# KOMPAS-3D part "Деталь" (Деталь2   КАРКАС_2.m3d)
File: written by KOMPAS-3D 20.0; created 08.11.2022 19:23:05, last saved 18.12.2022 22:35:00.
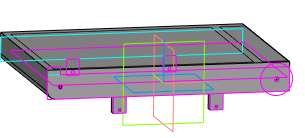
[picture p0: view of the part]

Document properties: Полное имя файла: C:\Users\Семья\Desktop\ДЕТАЛИ ДЛЯ СБОРЩИКА БОРЩЕВИКА\Деталь2   КАРКАС_2.m3d

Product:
- Part/product: Деталь
    Масса: 0.42166
  - Body: Тело 1
      Масса: 0.255433

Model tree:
1. Эскиз:1
2. Элемент выдавливания:1
     Расстояние 1 = 120
3. Плоскость через три точки:1
4. Плоскость через три точки:2
5. Эскиз:2
6. Элемент выдавливания:2
     Расстояние 2 = 10
7. Эскиз:5
8. Элемент выдавливания:4
     Расстояние 2 = 10
9. Эскиз:6
10. Эскиз:8
11. Элемент выдавливания:5
     Расстояние 1 = 15
12. Элемент выдавливания:6
     Расстояние 1 = 10
13. Эскиз:9  (with: Элемент выдавливания:1)
14. Элемент выдавливания:7
     Расстояние 2 = 5
15. Эскиз:10  (with: Элемент выдавливания:1)
16. Элемент выдавливания:8
     Расстояние 2 = 10
17. Эскиз:11  (with: Элемент выдавливания:1)
18. Элемент выдавливания:9
     Расстояние 2 = 5
19. Эскиз:12  (with: Элемент выдавливания:5)
20. Элемент выдавливания:10
     Расстояние 1 = 110
21. Эскиз:13  (with: Элемент выдавливания:1, Элемент выдавливания:2, Элемент выдавливания:9)
22. Эскиз:14  (with: Элемент выдавливания:1, Элемент выдавливания:9)
23. Элемент выдавливания:11
     Расстояние 2 = 120
24. Эскиз:15  (with: Элемент выдавливания:1)
25. Эскиз:16  (with: Элемент выдавливания:1, Элемент выдавливания:5, Элемент выдавливания:10)
26. Элемент выдавливания:12
     Расстояние 1 = 2.5
27. Эскиз:17  (with: Элемент выдавливания:12)
28. Элемент выдавливания:13
     Расстояние 1 = 0.5
29. Эскиз:18  (with: Элемент выдавливания:1)
30. Элемент выдавливания:14
     Расстояние 2 = 5
31. Эскиз:19  (with: Элемент выдавливания:1)
32. Элемент выдавливания:15
     Расстояние 2 = 5
33. Эскиз:20  (with: Элемент выдавливания:1)
34. Элемент выдавливания:16
     Расстояние 2 = 120
35. Скругление:1  (with: Элемент выдавливания:1)
     Радиус = 5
